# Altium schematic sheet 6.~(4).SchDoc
size 609 x 444 mm
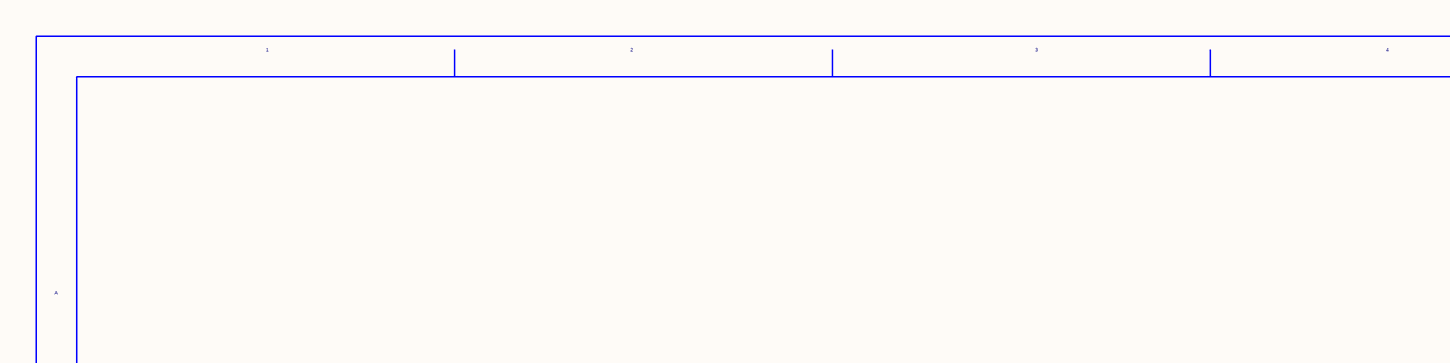
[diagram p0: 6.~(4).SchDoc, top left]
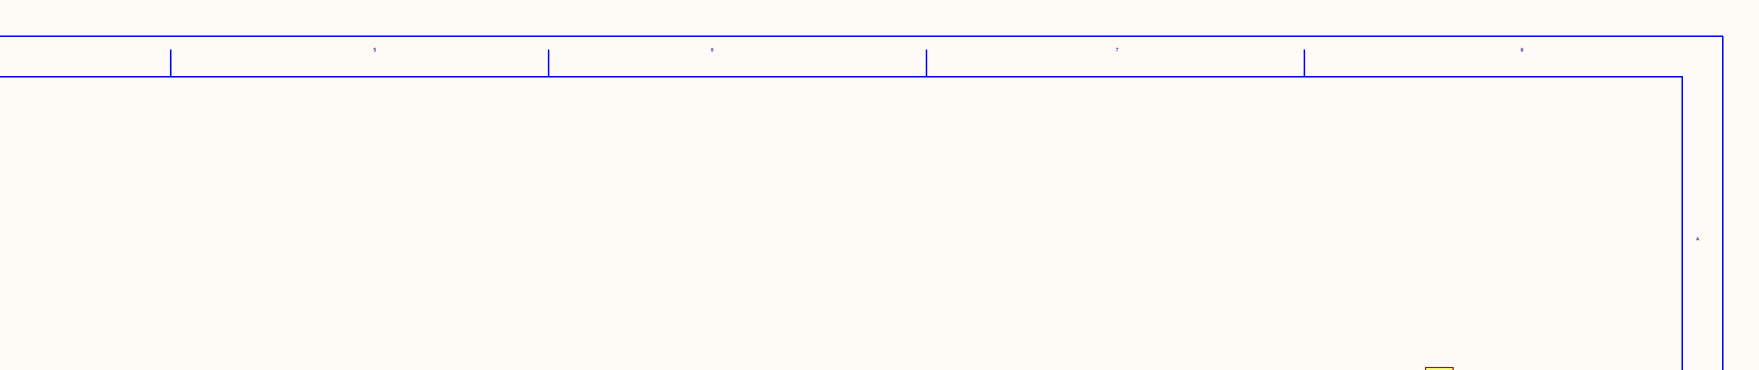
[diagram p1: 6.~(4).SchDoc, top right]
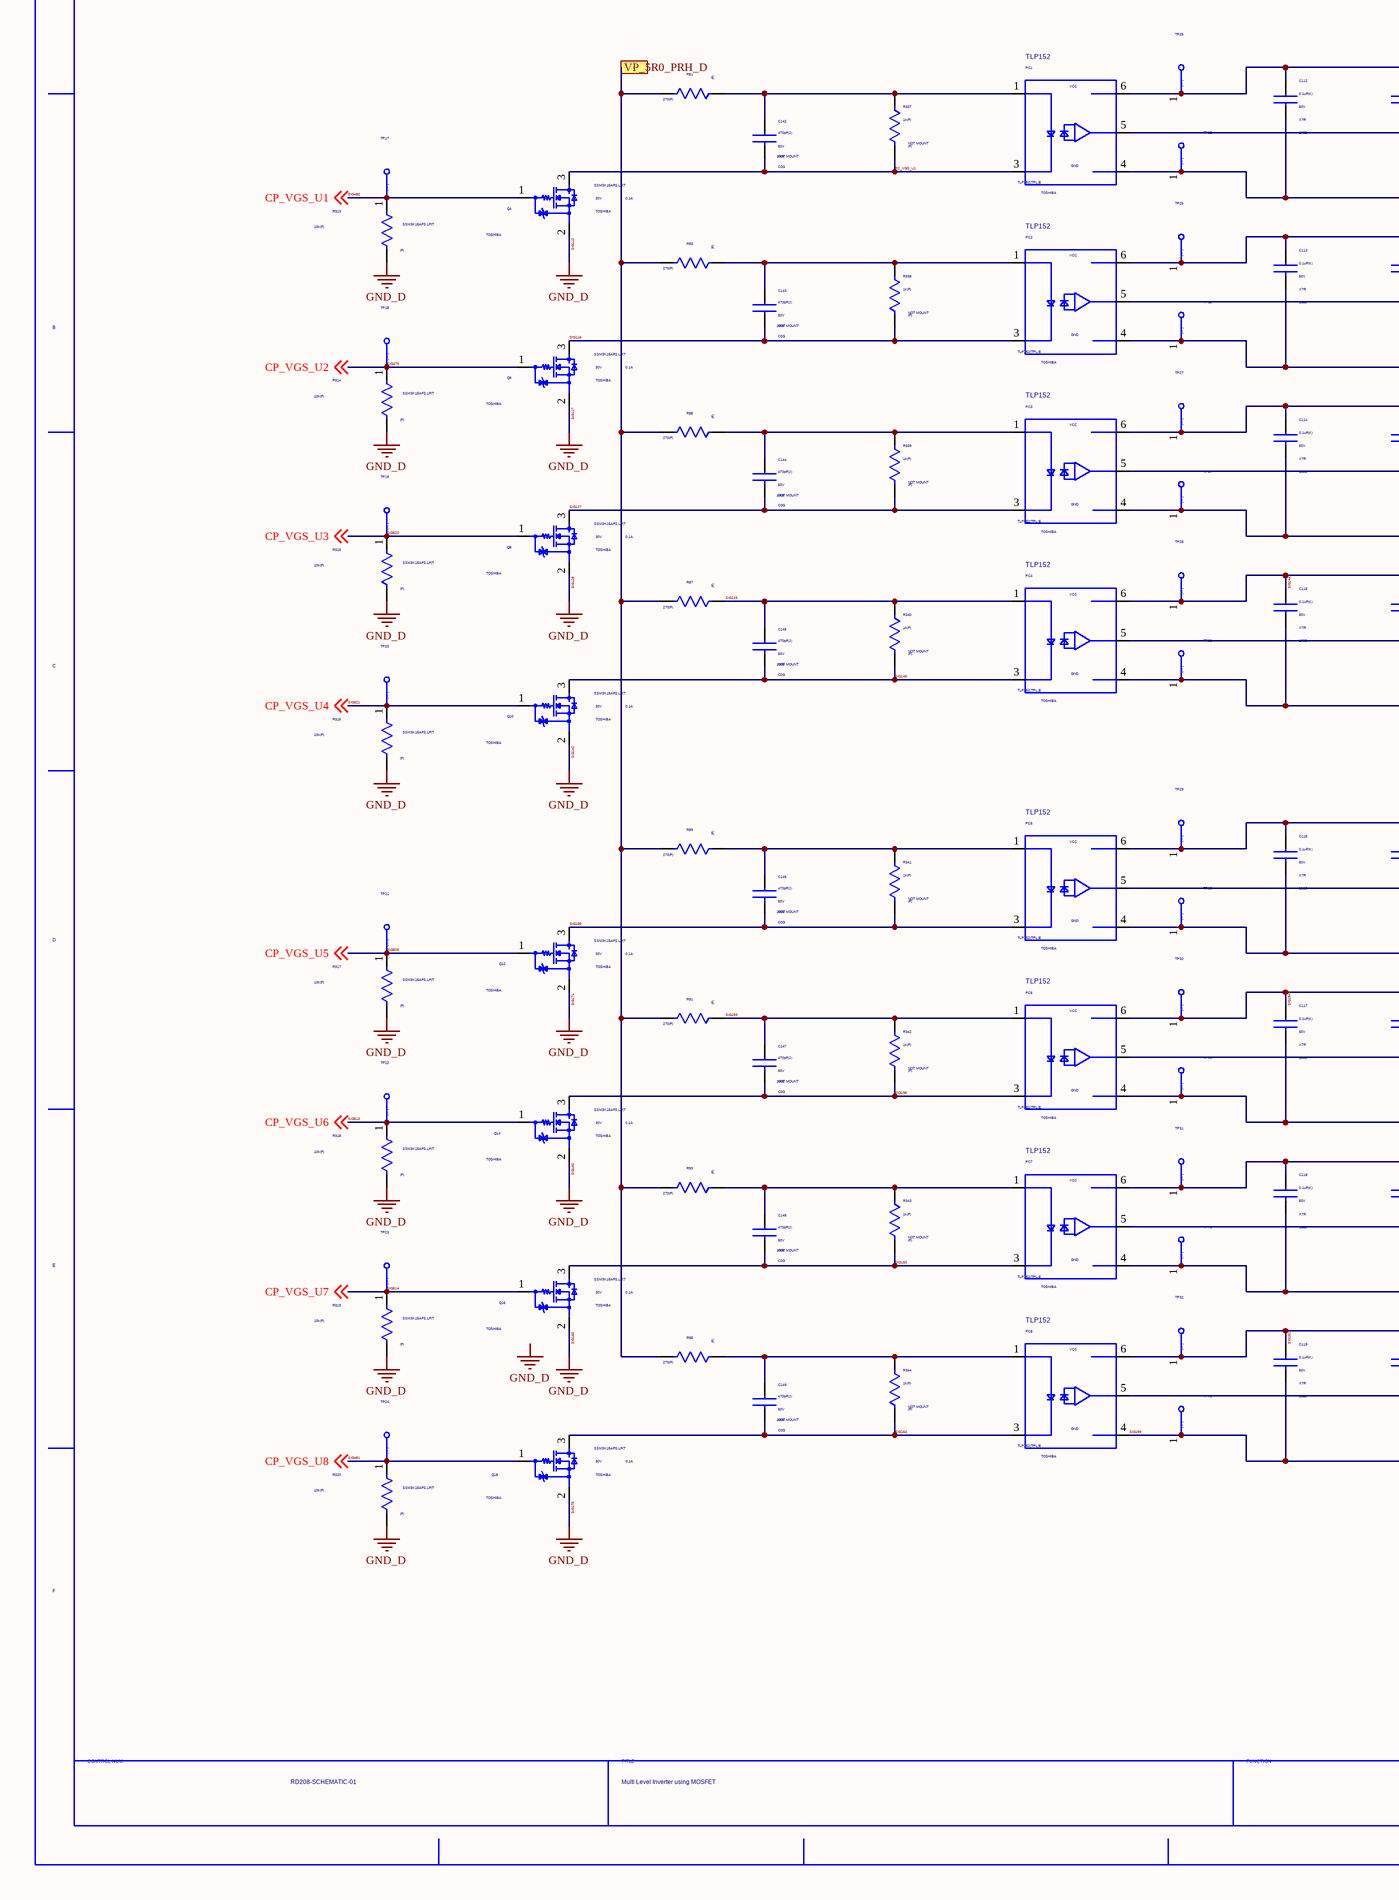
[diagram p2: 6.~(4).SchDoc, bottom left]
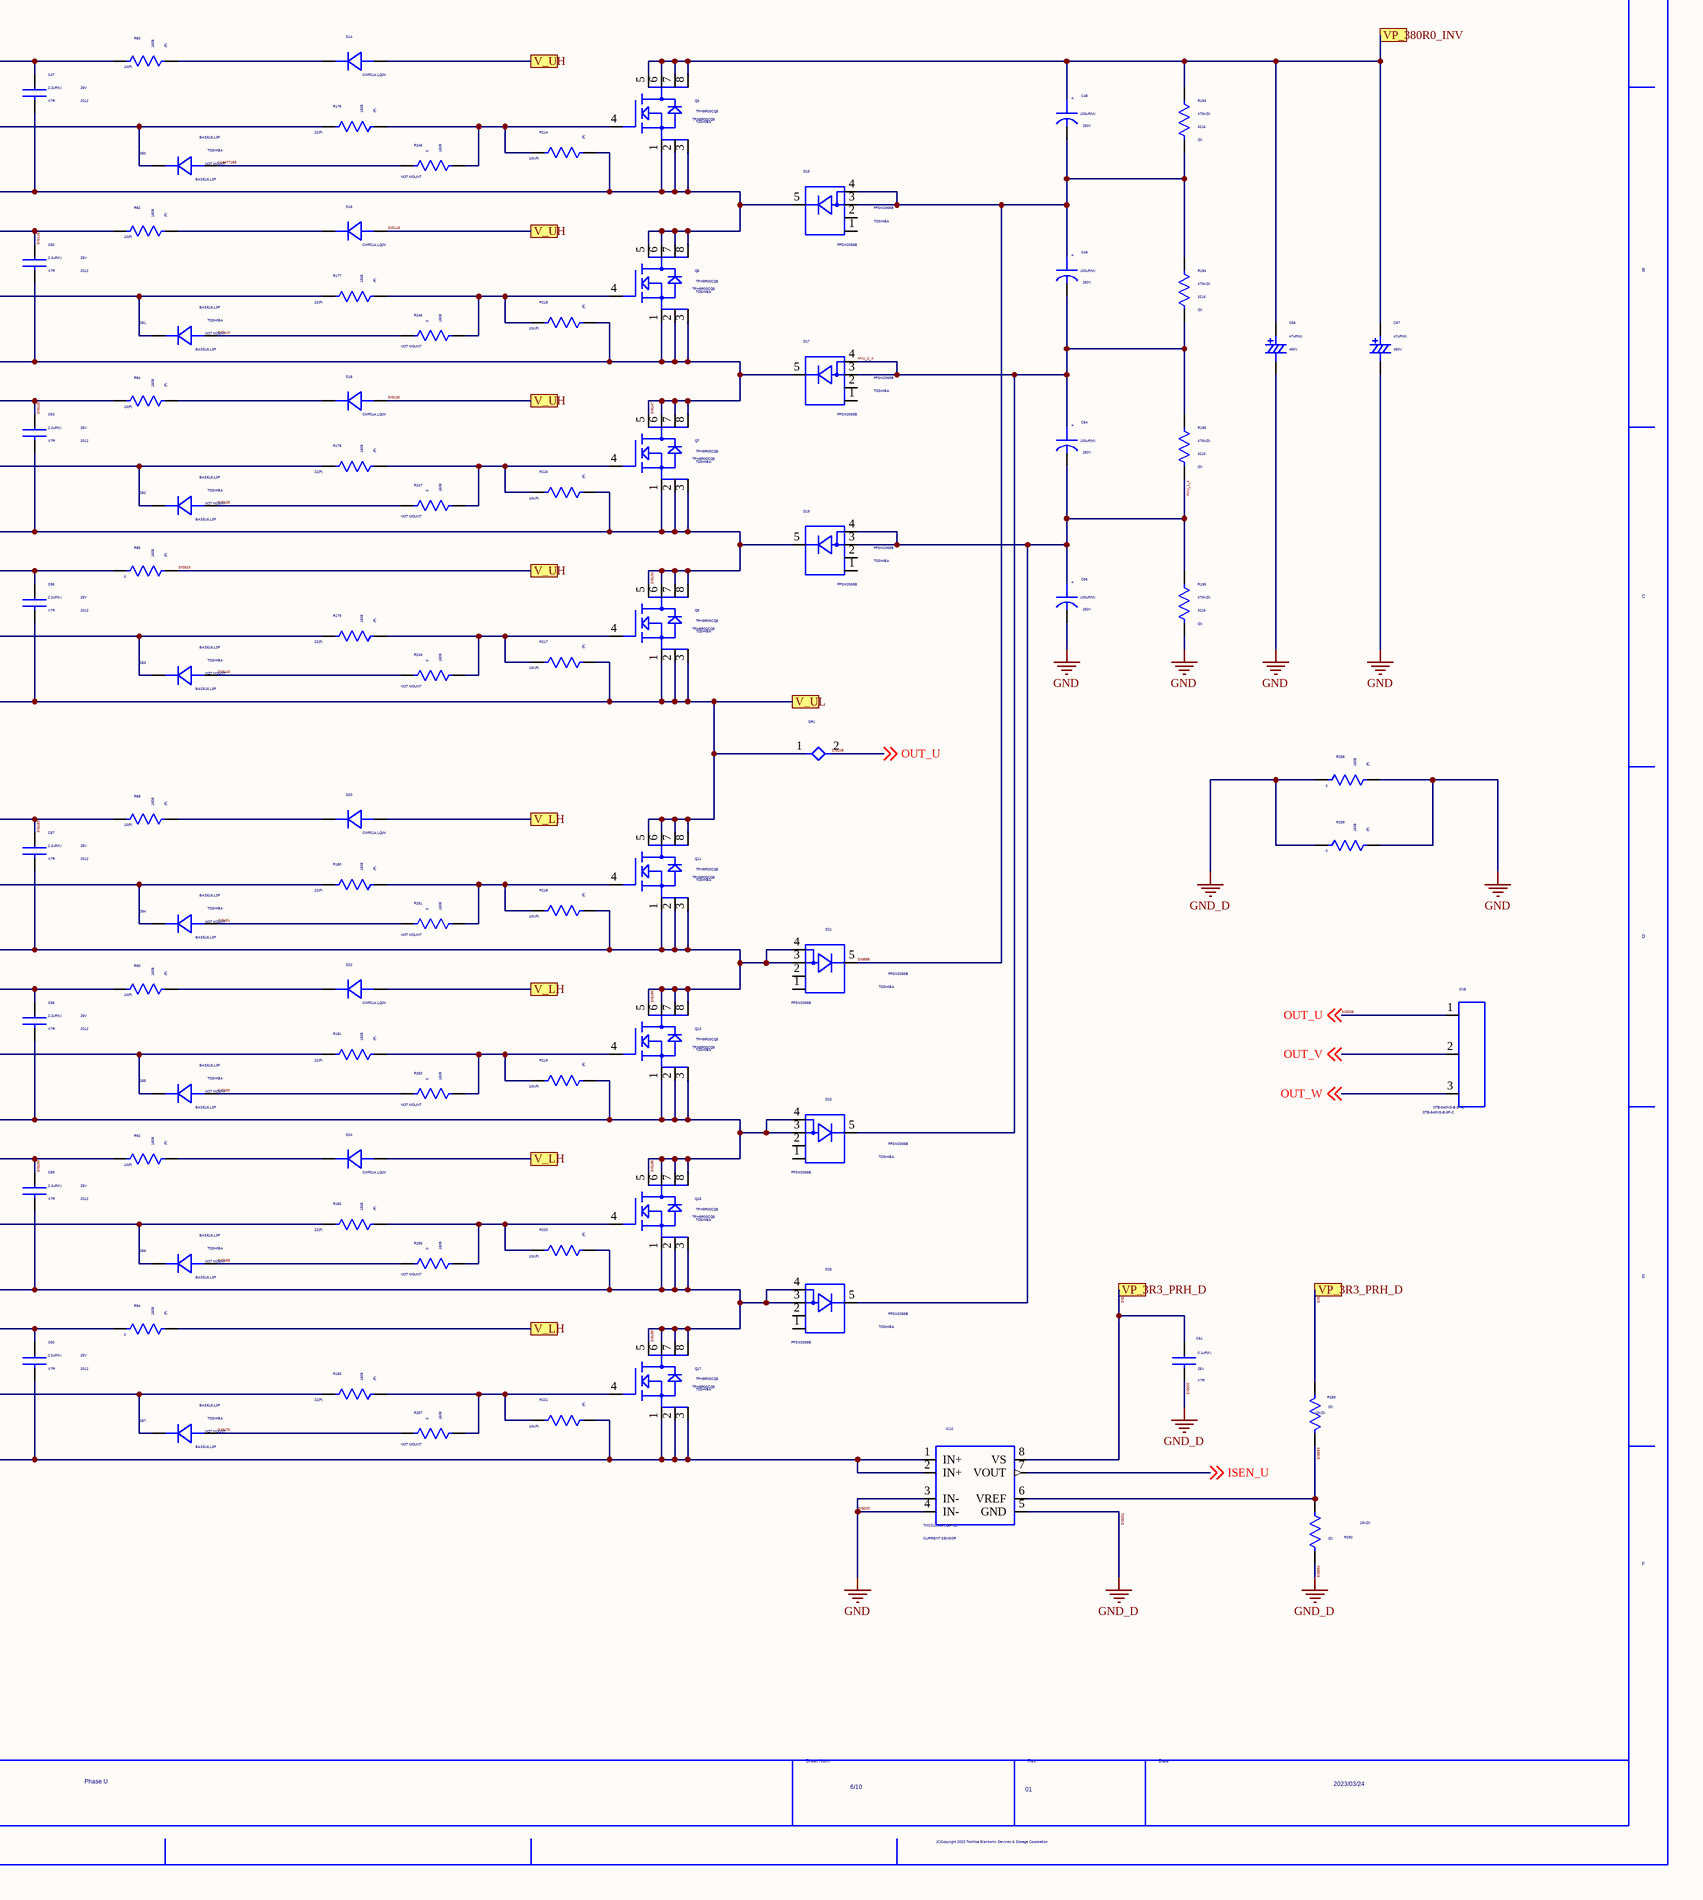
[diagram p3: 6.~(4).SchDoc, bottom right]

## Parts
C47  VAL2: 25V  SIZECODESMD: 2012  VALUE4: X7R  VAL1: 2.2uF(K)  (hidden comment: GRM21BR71E225KE11L)
C48  VAL2: 250V  VAL1: 100uF(M)  (hidden comment: EKMQ251ELL101ML25S)
C49  VAL2: 250V  VAL1: 100uF(M)  (hidden comment: EKMQ251ELL101ML25S)
C50  VAL2: 25V  SIZECODESMD: 2012  VALUE4: X7R  VAL1: 2.2uF(K)  (hidden comment: GRM21BR71E225KE11L)
C53  VAL2: 25V  SIZECODESMD: 2012  VALUE4: X7R  VAL1: 2.2uF(K)  (hidden comment: GRM21BR71E225KE11L)
C54  VAL2: 250V  VAL1: 100uF(M)  (hidden comment: EKMQ251ELL101ML25S)
C55  VAL2: 25V  SIZECODESMD: 2012  VALUE4: X7R  VAL1: 2.2uF(K)  (hidden comment: GRM21BR71E225KE11L)
C56  VAL2: 250V  VAL1: 100uF(M)  (hidden comment: EKMQ251ELL101ML25S)
C57  VAL2: 25V  SIZECODESMD: 2012  VALUE4: X7R  VAL1: 2.2uF(K)  (hidden comment: GRM21BR71E225KE11L)
C58  VAL2: 25V  SIZECODESMD: 2012  VALUE4: X7R  VAL1: 2.2uF(K)  (hidden comment: GRM21BR71E225KE11L)
C59  VAL2: 25V  SIZECODESMD: 2012  VALUE4: X7R  VAL1: 2.2uF(K)  (hidden comment: GRM21BR71E225KE11L)
C60  VAL2: 25V  SIZECODESMD: 2012  VALUE4: X7R  VAL1: 2.2uF(K)  (hidden comment: GRM21BR71E225KE11L)
C61  VAL2: 25V  VALUE4: X7R  VAL1: 0.1uF(K)  (hidden comment: GRM155R71E104KE14D)
C66  VAL2: 450V  VAL1: 47uF(M)  (hidden comment: EKXF451ELL470MM25S)
C67  VAL2: 450V  VAL1: 47uF(M)  (hidden comment: EKXF451ELL470MM25S)
C112  VAL2: 50V  SIZECODESMD: 1608  VALUE4: X7R  VAL1: 0.1uF(K)  (hidden comment: C1608X7R1H104K080AA)
C113  VAL2: 50V  SIZECODESMD: 1608  VALUE4: X7R  VAL1: 0.1uF(K)  (hidden comment: C1608X7R1H104K080AA)
C114  VAL2: 50V  SIZECODESMD: 1608  VALUE4: X7R  VAL1: 0.1uF(K)  (hidden comment: C1608X7R1H104K080AA)
C115  VAL2: 50V  SIZECODESMD: 1608  VALUE4: X7R  VAL1: 0.1uF(K)  (hidden comment: C1608X7R1H104K080AA)
C116  VAL2: 50V  SIZECODESMD: 1608  VALUE4: X7R  VAL1: 0.1uF(K)  (hidden comment: C1608X7R1H104K080AA)
C117  VAL2: 50V  SIZECODESMD: 1608  VALUE4: X7R  VAL1: 0.1uF(K)  (hidden comment: C1608X7R1H104K080AA)
C118  VAL2: 50V  SIZECODESMD: 1608  VALUE4: X7R  VAL1: 0.1uF(K)  (hidden comment: C1608X7R1H104K080AA)
C119  VAL2: 50V  SIZECODESMD: 1608  VALUE4: X7R  VAL1: 0.1uF(K)  (hidden comment: C1608X7R1H104K080AA)
C142  VAL2: 50V  SIZECODESMD: 1005  VALUE4: C0G  VAL1: 470pF(J)  NOTMOUNT: NOT MOUNT  (hidden comment: GRM1555C1H471JA01J)
C143  VAL2: 50V  SIZECODESMD: 1005  VALUE4: C0G  VAL1: 470pF(J)  NOTMOUNT: NOT MOUNT  (hidden comment: GRM1555C1H471JA01J)
C144  VAL2: 50V  SIZECODESMD: 1005  VALUE4: C0G  VAL1: 470pF(J)  NOTMOUNT: NOT MOUNT  (hidden comment: GRM1555C1H471JA01J)
C145  VAL2: 50V  SIZECODESMD: 1005  VALUE4: C0G  VAL1: 470pF(J)  NOTMOUNT: NOT MOUNT  (hidden comment: GRM1555C1H471JA01J)
C146  VAL2: 50V  SIZECODESMD: 1005  VALUE4: C0G  VAL1: 470pF(J)  NOTMOUNT: NOT MOUNT  (hidden comment: GRM1555C1H471JA01J)
C147  VAL2: 50V  SIZECODESMD: 1005  VALUE4: C0G  VAL1: 470pF(J)  NOTMOUNT: NOT MOUNT  (hidden comment: GRM1555C1H471JA01J)
C148  VAL2: 50V  SIZECODESMD: 1005  VALUE4: C0G  VAL1: 470pF(J)  NOTMOUNT: NOT MOUNT  (hidden comment: GRM1555C1H471JA01J)
C149  VAL2: 50V  SIZECODESMD: 1005  VALUE4: C0G  VAL1: 470pF(J)  NOTMOUNT: NOT MOUNT  (hidden comment: GRM1555C1H471JA01J)
CN5  VAL1: OTB-640NS-B-3P-C  (hidden comment: OTB_640NS_B_3P_C)
D14  VAL1: CMF01A,LQ(M  (hidden comment: CMF01A,LQ_M)
D15  USERCOMPTEXT3: TOSHIBA  (hidden comment: FFSM2065B)
D16  VAL1: CMF01A,LQ(M  (hidden comment: CMF01A,LQ_M)
D17  USERCOMPTEXT3: TOSHIBA  (hidden comment: FFSM2065B)
D18  VAL1: CMF01A,LQ(M  (hidden comment: CMF01A,LQ_M)
D19  USERCOMPTEXT3: TOSHIBA  (hidden comment: FFSM2065B)
D20  VAL1: CMF01A,LQ(M  (hidden comment: CMF01A,LQ_M)
D21  USERCOMPTEXT3: TOSHIBA  (hidden comment: FFSM2065B)
D22  VAL1: CMF01A,LQ(M  (hidden comment: CMF01A,LQ_M)
D23  USERCOMPTEXT3: TOSHIBA  (hidden comment: FFSM2065B)
D24  VAL1: CMF01A,LQ(M  (hidden comment: CMF01A,LQ_M)
D25  USERCOMPTEXT3: TOSHIBA  (hidden comment: FFSM2065B)
D50  USERCOMPTEXT3: TOSHIBA  NOTMOUNT: NOT MOUNT  (hidden comment: BAS516,L3F)
D51  USERCOMPTEXT3: TOSHIBA  NOTMOUNT: NOT MOUNT  (hidden comment: BAS516,L3F)
D52  USERCOMPTEXT3: TOSHIBA  NOTMOUNT: NOT MOUNT  (hidden comment: BAS516,L3F)
D53  USERCOMPTEXT3: TOSHIBA  NOTMOUNT: NOT MOUNT  (hidden comment: BAS516,L3F)
D54  USERCOMPTEXT3: TOSHIBA  NOTMOUNT: NOT MOUNT  (hidden comment: BAS516,L3F)
D55  USERCOMPTEXT3: TOSHIBA  NOTMOUNT: NOT MOUNT  (hidden comment: BAS516,L3F)
D56  USERCOMPTEXT3: TOSHIBA  NOTMOUNT: NOT MOUNT  (hidden comment: BAS516,L3F)
D57  USERCOMPTEXT3: TOSHIBA  NOTMOUNT: NOT MOUNT  (hidden comment: BAS516,L3F)
DR1  STAR2  (value not drawn)
IC10  VAL2: CURRENT SENSOR  (hidden comment: TMCS1100A1QDRQ1)
PC1  SCH_NAME: TLP152  USERCOMPTEXT3: TOSHIBA  VAL3: TLP152(TPL,E  (hidden comment: TLP152_TPL,E)
PC2  SCH_NAME: TLP152  USERCOMPTEXT3: TOSHIBA  VAL3: TLP152(TPL,E  (hidden comment: TLP152_TPL,E)
PC3  SCH_NAME: TLP152  USERCOMPTEXT3: TOSHIBA  VAL3: TLP152(TPL,E  (hidden comment: TLP152_TPL,E)
PC4  SCH_NAME: TLP152  USERCOMPTEXT3: TOSHIBA  VAL3: TLP152(TPL,E  (hidden comment: TLP152_TPL,E)
PC5  SCH_NAME: TLP152  USERCOMPTEXT3: TOSHIBA  VAL3: TLP152(TPL,E  (hidden comment: TLP152_TPL,E)
PC6  SCH_NAME: TLP152  USERCOMPTEXT3: TOSHIBA  VAL3: TLP152(TPL,E  (hidden comment: TLP152_TPL,E)
PC7  SCH_NAME: TLP152  USERCOMPTEXT3: TOSHIBA  VAL3: TLP152(TPL,E  (hidden comment: TLP152_TPL,E)
PC8  SCH_NAME: TLP152  USERCOMPTEXT3: TOSHIBA  VAL3: TLP152(TPL,E  (hidden comment: TLP152_TPL,E)
Q3  USERCOMPTEXT3: TOSHIBA  (hidden comment: TPH9R00CQ5)
Q4  VAL2: 0.1A  MANUFACTURER: TOSHIBA  SIZECODESMD: 30V  VAL1: SSM3K15AFS,LF(T  (hidden comment: SSM3K15AFS,LF_T)
Q5  USERCOMPTEXT3: TOSHIBA  (hidden comment: TPH9R00CQ5)
Q6  VAL2: 0.1A  MANUFACTURER: TOSHIBA  SIZECODESMD: 30V  VAL1: SSM3K15AFS,LF(T  (hidden comment: SSM3K15AFS,LF_T)
Q7  USERCOMPTEXT3: TOSHIBA  (hidden comment: TPH9R00CQ5)
Q8  VAL2: 0.1A  MANUFACTURER: TOSHIBA  SIZECODESMD: 30V  VAL1: SSM3K15AFS,LF(T  (hidden comment: SSM3K15AFS,LF_T)
Q9  USERCOMPTEXT3: TOSHIBA  (hidden comment: TPH9R00CQ5)
Q10  VAL2: 0.1A  MANUFACTURER: TOSHIBA  SIZECODESMD: 30V  VAL1: SSM3K15AFS,LF(T  (hidden comment: SSM3K15AFS,LF_T)
Q11  USERCOMPTEXT3: TOSHIBA  (hidden comment: TPH9R00CQ5)
Q12  VAL2: 0.1A  MANUFACTURER: TOSHIBA  SIZECODESMD: 30V  VAL1: SSM3K15AFS,LF(T  (hidden comment: SSM3K15AFS,LF_T)
Q13  USERCOMPTEXT3: TOSHIBA  (hidden comment: TPH9R00CQ5)
Q14  VAL2: 0.1A  MANUFACTURER: TOSHIBA  SIZECODESMD: 30V  VAL1: SSM3K15AFS,LF(T  (hidden comment: SSM3K15AFS,LF_T)
Q15  USERCOMPTEXT3: TOSHIBA  (hidden comment: TPH9R00CQ5)
Q16  VAL2: 0.1A  MANUFACTURER: TOSHIBA  SIZECODESMD: 30V  VAL1: SSM3K15AFS,LF(T  (hidden comment: SSM3K15AFS,LF_T)
Q17  USERCOMPTEXT3: TOSHIBA  (hidden comment: TPH9R00CQ5)
Q18  VAL2: 0.1A  MANUFACTURER: TOSHIBA  SIZECODESMD: 30V  VAL1: SSM3K15AFS,LF(T  (hidden comment: SSM3K15AFS,LF_T)
R80  SIZECODESMD: 1608  VALUE4: (F)  VAL1: 10(F)  (hidden comment: ERJ3EKF10R0V)
R81  VALUE4: (F)  VAL1: 270(F)  (hidden comment: ERJ2RKF2700X)
R82  SIZECODESMD: 1608  VALUE4: (F)  VAL1: 10(F)  (hidden comment: ERJ3EKF10R0V)
R83  VALUE4: (F)  VAL1: 270(F)  (hidden comment: ERJ2RKF2700X)
R84  SIZECODESMD: 1608  VALUE4: (F)  VAL1: 10(F)  (hidden comment: ERJ3EKF10R0V)
R85  VALUE4: (F)  VAL1: 270(F)  (hidden comment: ERJ2RKF2700X)
R86  SIZECODESMD: 1608  VALUE4: (F)  VAL1: 0  (hidden comment: ERJ3EKF10R0V)
R87  VALUE4: (F)  VAL1: 270(F)  (hidden comment: ERJ2RKF2700X)
R88  SIZECODESMD: 1608  VALUE4: (F)  VAL1: 10(F)  (hidden comment: ERJ3EKF10R0V)
R89  VALUE4: (F)  VAL1: 270(F)  (hidden comment: ERJ2RKF2700X)
R90  SIZECODESMD: 1608  VALUE4: (F)  VAL1: 10(F)  (hidden comment: ERJ3EKF10R0V)
R91  VALUE4: (F)  VAL1: 270(F)  (hidden comment: ERJ2RKF2700X)
R92  SIZECODESMD: 1608  VALUE4: (F)  VAL1: 10(F)  (hidden comment: ERJ3EKF10R0V)
R93  VALUE4: (F)  VAL1: 270(F)  (hidden comment: ERJ2RKF2700X)
R94  SIZECODESMD: 1608  VALUE4: (F)  VAL1: 0  (hidden comment: ERJ3EKF10R0V)
R95  VALUE4: (F)  VAL1: 270(F)  (hidden comment: ERJ2RKF2700X)
R176  SIZECODESMD: 1608  VALUE4: (F)  VAL1: 22(F)  (hidden comment: ERJ3EKF22R0V)
R177  SIZECODESMD: 1608  VALUE4: (F)  VAL1: 22(F)  (hidden comment: ERJ3EKF22R0V)
R178  SIZECODESMD: 1608  VALUE4: (F)  VAL1: 22(F)  (hidden comment: ERJ3EKF22R0V)
R179  SIZECODESMD: 1608  VALUE4: (F)  VAL1: 22(F)  (hidden comment: ERJ3EKF22R0V)
R180  SIZECODESMD: 1608  VALUE4: (F)  VAL1: 22(F)  (hidden comment: ERJ3EKF22R0V)
R181  SIZECODESMD: 1608  VALUE4: (F)  VAL1: 22(F)  (hidden comment: ERJ3EKF22R0V)
R182  SIZECODESMD: 1608  VALUE4: (F)  VAL1: 22(F)  (hidden comment: ERJ3EKF22R0V)
R183  SIZECODESMD: 1608  VALUE4: (F)  VAL1: 22(F)  (hidden comment: ERJ3EKF22R0V)
R193  SIZECODESMD: 3216  VALUE4: (D)  VAL1: 470k(D)  (hidden comment: HV73V2BTTD4703D)
R194  SIZECODESMD: 3216  VALUE4: (D)  VAL1: 470k(D)  (hidden comment: HV73V2BTTD4703D)
R195  SIZECODESMD: 3216  VALUE4: (D)  VAL1: 470k(D)  (hidden comment: HV73V2BTTD4703D)
R196  SIZECODESMD: 3216  VALUE4: (D)  VAL1: 470k(D)  (hidden comment: HV73V2BTTD4703D)
R214  VALUE4: (F)  VAL1: 10k(F)  (hidden comment: ERJ2RKF1002X)
R215  VALUE4: (F)  VAL1: 10k(F)  (hidden comment: ERJ2RKF1002X)
R216  VALUE4: (F)  VAL1: 10k(F)  (hidden comment: ERJ2RKF1002X)
R217  VALUE4: (F)  VAL1: 10k(F)  (hidden comment: ERJ2RKF1002X)
R218  VALUE4: (F)  VAL1: 10k(F)  (hidden comment: ERJ2RKF1002X)
R219  VALUE4: (F)  VAL1: 10k(F)  (hidden comment: ERJ2RKF1002X)
R220  VALUE4: (F)  VAL1: 10k(F)  (hidden comment: ERJ2RKF1002X)
R221  VALUE4: (F)  VAL1: 10k(F)  (hidden comment: ERJ2RKF1002X)
R245  SIZECODESMD: 1608  VAL1: 0  NOTMOUNT: NOT MOUNT  (hidden comment: ERJ3GEY0R00V)
R246  SIZECODESMD: 1608  VAL1: 0  NOTMOUNT: NOT MOUNT  (hidden comment: ERJ3GEY0R00V)
R247  SIZECODESMD: 1608  VAL1: 0  NOTMOUNT: NOT MOUNT  (hidden comment: ERJ3GEY0R00V)
R249  SIZECODESMD: 1608  VAL1: 0  NOTMOUNT: NOT MOUNT  (hidden comment: ERJ3GEY0R00V)
R251  SIZECODESMD: 1608  VAL1: 0  NOTMOUNT: NOT MOUNT  (hidden comment: ERJ3GEY0R00V)
R253  SIZECODESMD: 1608  VAL1: 0  NOTMOUNT: NOT MOUNT  (hidden comment: ERJ3GEY0R00V)
R255  SIZECODESMD: 1608  VAL1: 0  NOTMOUNT: NOT MOUNT  (hidden comment: ERJ3GEY0R00V)
R257  SIZECODESMD: 1608  VAL1: 0  NOTMOUNT: NOT MOUNT  (hidden comment: ERJ3GEY0R00V)
R289  VALUE4: (D)  VAL1: 10k(D)  (hidden comment: RK73G1ETTP1002D)
R290  VALUE4: (D)  VAL1: 10k(D)  (hidden comment: RK73G1ETTP1002D)
R298  SIZECODESMD: 1608  VALUE4: (F)  VAL1: 0  (hidden comment: ERJ3EKF10R0V)
R299  SIZECODESMD: 1608  VALUE4: (F)  VAL1: 0  (hidden comment: ERJ3EKF10R0V)
R313  VALUE4: (F)  VAL1: 10k(F)  (hidden comment: ERJ2RKF1002X)
R314  VALUE4: (F)  VAL1: 10k(F)  (hidden comment: ERJ2RKF1002X)
R315  VALUE4: (F)  VAL1: 10k(F)  (hidden comment: ERJ2RKF1002X)
R316  VALUE4: (F)  VAL1: 10k(F)  (hidden comment: ERJ2RKF1002X)
R317  VALUE4: (F)  VAL1: 10k(F)  (hidden comment: ERJ2RKF1002X)
R318  VALUE4: (F)  VAL1: 10k(F)  (hidden comment: ERJ2RKF1002X)
R319  VALUE4: (F)  VAL1: 10k(F)  (hidden comment: ERJ2RKF1002X)
R320  VALUE4: (F)  VAL1: 10k(F)  (hidden comment: ERJ2RKF1002X)
R337  VALUE4: (F)  VAL1: 1k(F)  NOTMOUNT: NOT MOUNT  (hidden comment: ERJ2RKF1001X)
R338  VALUE4: (F)  VAL1: 1k(F)  NOTMOUNT: NOT MOUNT  (hidden comment: ERJ2RKF1001X)
R339  VALUE4: (F)  VAL1: 1k(F)  NOTMOUNT: NOT MOUNT  (hidden comment: ERJ2RKF1001X)
R340  VALUE4: (F)  VAL1: 1k(F)  NOTMOUNT: NOT MOUNT  (hidden comment: ERJ2RKF1001X)
R341  VALUE4: (F)  VAL1: 1k(F)  NOTMOUNT: NOT MOUNT  (hidden comment: ERJ2RKF1001X)
R342  VALUE4: (F)  VAL1: 1k(F)  NOTMOUNT: NOT MOUNT  (hidden comment: ERJ2RKF1001X)
R343  VALUE4: (F)  VAL1: 1k(F)  NOTMOUNT: NOT MOUNT  (hidden comment: ERJ2RKF1001X)
R344  VALUE4: (F)  VAL1: 1k(F)  NOTMOUNT: NOT MOUNT  (hidden comment: ERJ2RKF1001X)
TP17  TP  (value not drawn)
TP18  TP  (value not drawn)
TP19  TP  (value not drawn)
TP20  TP  (value not drawn)
TP21  TP  (value not drawn)
TP22  TP  (value not drawn)
TP23  TP  (value not drawn)
TP24  TP  (value not drawn)
TP25  TP  (value not drawn)
TP26  TP  (value not drawn)
TP27  TP  (value not drawn)
TP28  TP  (value not drawn)
TP29  TP  (value not drawn)
TP30  TP  (value not drawn)
TP31  TP  (value not drawn)
TP32  TP  (value not drawn)
TP65  TP  (value not drawn)
TP66  TP  (value not drawn)
TP67  TP  (value not drawn)
TP68  TP  (value not drawn)
TP69  TP  (value not drawn)
TP70  TP  (value not drawn)
TP71  TP  (value not drawn)
TP72  TP  (value not drawn)
U?  DATE: 2023/03/24  TITLE: Multi Level Inverter using MOSFET  REVISION: 01  SHEETNUMBER: 6/10  DRAWINGNUMBER: RD208-SCHEMATIC-01  FUNCTION: Phase U  (hidden comment: WAKU_DEF_A3)

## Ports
V_LH, V_UH, V_UL, VP_3R3_PRH_D, VP_5R0_PRH_D, VP_380R0_INV

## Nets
SIG112: C61.2 IC10.5(GND) Q4.2(E) Q6.2(E) Q8.2(E) Q10.2(E) Q12.2(E) Q14.2(E) Q16.2(E) Q18.2(E) R290.2 R298.1 R299.1 R313.2 R314.2 R315.2 R316.2 R317.2 R318.2 R319.2 R320.2  [also labelled GND_D, SIG117, SIG128, SIG142, SIG160, SIG171, SIG175, SIG192, SIG201, SIG202, SIG554]
SIG200: C56.2 C66.2 C67.2 IC10.3(IN-) IC10.4(IN-) R196.2 R298.2 R299.2  [also labelled GND]
BS_U1: D14.K(CATHODE) R80.2
GD_U1: Q3.4(G) R176.2 R214.1 R245.2
GD_U2: Q5.4(G) R177.2 R215.1 R246.2
GD_U3: Q7.4(G) R178.2 R216.1 R247.2
GD_U5: Q11.4(G) R180.2 R218.1 R251.2
GD_U6: Q13.4(G) R181.2 R219.1 R253.2
GD_U7: Q15.4(G) R182.2 R220.1 R255.2
GD_U8: Q17.4(G) R183.2 R221.1 R257.2
HVU_1_4: C54.2 C56.1 D19.3(ANODE3) D19.4(ANODE4) D25.5(CATHODE) R195.2 R196.1
HVU_2_4: C49.2 C54.1 D17.3(ANODE3) D17.4(ANODE4) D23.5(CATHODE) R194.2 R195.1
ISEN_U: IC10.7(VOUT) ; off-sheet ISEN_U
N16677268: D50.A(ANODE) R245.1
OUT_V: CN5.2 ; off-sheet OUT_V
OUT_W: CN5.3 ; off-sheet OUT_W
PC_ANODE_U1: C142.1 PC1.1 R81.2 R337.1
PC_G_U1: C47.2 C112.2 D15.5(CATHODE) PC1.4 Q3.1(S1) Q3.2(S2) Q3.3(S3) Q5.5(D1) Q5.6(D2) Q5.7(D3) Q5.8(D4) R214.2 TP65.1
PC_GD_U1: D50.K(CATHODE) PC1.5 R176.1
PC_V_U1: C47.1 C112.1 PC1.6 R80.1 TP25.1
PC_VGS_U1: C142.2 PC1.3 Q4.3(C) R337.2
SIG113: C143.1 PC2.1 R83.2 R338.1
SIG114: D51.A(ANODE) R246.1
SIG115: C50.1 C113.1 PC2.6 R82.1 TP26.1
SIG116: C143.2 PC2.3 Q6.3(C) R338.2
SIG119: D14.A(ANODE) D16.A(ANODE) D18.A(ANODE) R86.2 ; port V_UH  [also labelled SIG130, SIG323]
SIG122: D51.K(CATHODE) PC2.5 R177.1
SIG123: D16.K(CATHODE) R82.2
SIG124: C144.1 PC3.1 R85.2 R339.1
SIG125: D52.A(ANODE) R247.1
SIG126: C53.1 C114.1 PC3.6 R84.1 TP27.1
SIG127: C144.2 PC3.3 Q8.3(C) R339.2
SIG133: C53.2 C114.2 D19.5(CATHODE) PC3.4 Q7.1(S1) Q7.2(S2) Q7.3(S3) Q9.5(D1) Q9.6(D2) Q9.7(D3) Q9.8(D4) R216.2 TP67.1
SIG134: D52.K(CATHODE) PC3.5 R178.1
SIG136: D53.K(CATHODE) PC4.5 R179.1
SIG137: D18.K(CATHODE) R84.2
SIG140: D53.A(ANODE) R249.1
SIG143: C145.1 PC4.1 R87.2 R340.1
SIG144: C55.1 C115.1 PC4.6 R86.1 TP28.1
SIG145: Q9.4(G) R179.2 R217.1 R249.2
SIG146: C145.2 PC4.3 Q10.3(C) R340.2
SIG147: C50.2 C113.2 D17.5(CATHODE) PC2.4 Q5.1(S1) Q5.2(S2) Q5.3(S3) Q7.5(D1) Q7.6(D2) Q7.7(D3) Q7.8(D4) R215.2 TP66.1
SIG149: C146.1 PC5.1 R89.2 R341.1
SIG150: C59.2 C118.2 D25.3(ANODE3) D25.4(ANODE4) PC7.4 Q15.1(S1) Q15.2(S2) Q15.3(S3) Q17.5(D1) Q17.6(D2) Q17.7(D3) Q17.8(D4) R220.2 TP71.1
SIG151: D54.A(ANODE) R251.1
SIG153: C148.2 PC7.3 Q16.3(C) R343.2
SIG154: C148.1 PC7.1 R93.2 R343.1
SIG156: C59.1 C118.1 PC7.6 R92.1 TP31.1
SIG158: D56.A(ANODE) R255.1
SIG161: C60.1 C119.1 PC8.6 R94.1 TP32.1
SIG163: C57.1 C116.1 PC5.6 R88.1 TP29.1
SIG164: C149.2 PC8.3 Q18.3(C) R344.2
SIG165: C146.2 PC5.3 Q12.3(C) R341.2
SIG166: D57.K(CATHODE) PC8.5 R183.1
SIG170: D57.A(ANODE) R257.1
SIG174: C149.1 PC8.1 R95.2 R344.1
SIG176: D24.K(CATHODE) R92.2
SIG180: C57.2 C116.2 D21.3(ANODE3) D21.4(ANODE4) PC5.4 Q11.1(S1) Q11.2(S2) Q11.3(S3) Q13.5(D1) Q13.6(D2) Q13.7(D3) Q13.8(D4) R218.2 TP69.1
SIG182: D54.K(CATHODE) PC5.5 R180.1
SIG183: D22.K(CATHODE) R90.2
SIG184: D56.K(CATHODE) PC7.5 R182.1
SIG185: C58.2 C117.2 D23.3(ANODE3) D23.4(ANODE4) PC6.4 Q13.1(S1) Q13.2(S2) Q13.3(S3) Q15.5(D1) Q15.6(D2) Q15.7(D3) Q15.8(D4) R219.2 TP70.1
SIG186: D55.K(CATHODE) PC6.5 R181.1
SIG187: D20.K(CATHODE) R88.2
SIG190: D55.A(ANODE) R253.1
SIG193: C147.1 PC6.1 R91.2 R342.1
SIG194: C58.1 C117.1 PC6.6 R90.1 TP30.1
SIG196: C147.2 PC6.3 Q14.3(C) R342.2
SIG199: C60.2 C119.2 IC10.1(IN+) IC10.2(IN+) PC8.4 Q17.1(S1) Q17.2(S2) Q17.3(S3) R221.2 TP72.1
SIG203: C61.1 IC10.8(VS) R289.2 ; port VP_3R3_PRH_D  [also labelled SIG204]
SIG208: CN5.1 DR1.2 ; off-sheet OUT_U  [also labelled OUT_U]
SIG479: Q6.1(B) R314.1 TP18.1 ; off-sheet CP_VGS_U2  [also labelled CP_VGS_U2]
SIG480: Q4.1(B) R313.1 TP17.1 ; off-sheet CP_VGS_U1  [also labelled CP_VGS_U1]
SIG481: Q18.1(B) R320.1 TP24.1 ; off-sheet CP_VGS_U8  [also labelled CP_VGS_U8]
SIG509: Q12.1(B) R317.1 TP21.1 ; off-sheet CP_VGS_U5  [also labelled CP_VGS_U5]
SIG513: Q14.1(B) R318.1 TP22.1 ; off-sheet CP_VGS_U6  [also labelled CP_VGS_U6]
SIG514: Q16.1(B) R319.1 TP23.1 ; off-sheet CP_VGS_U7  [also labelled CP_VGS_U7]
SIG521: Q10.1(B) R316.1 TP20.1 ; off-sheet CP_VGS_U4  [also labelled CP_VGS_U4]
SIG522: Q8.1(B) R315.1 TP19.1 ; off-sheet CP_VGS_U3  [also labelled CP_VGS_U3]
SIG553: IC10.6(VREF) R289.1 R290.1
SIG555: C48.2 C49.1 D15.3(ANODE3) D15.4(ANODE4) D21.5(CATHODE) R193.2 R194.1
V_LH: D20.A(ANODE) D22.A(ANODE) D24.A(ANODE) R94.2 ; port V_LH
V_UL: C55.2 C115.2 DR1.1 PC4.4 Q9.1(S1) Q9.2(S2) Q9.3(S3) Q11.5(D1) Q11.6(D2) Q11.7(D3) Q11.8(D4) R217.2 TP68.1 ; port V_UL
VP_5R0_PRH_D: R81.1 R83.1 R85.1 R87.1 R89.1 R91.1 R93.1 R95.1 ; port VP_5R0_PRH_D
VP_380R0_INV: C48.1 C66.1 C67.1 Q3.5(D1) Q3.6(D2) Q3.7(D3) Q3.8(D4) R193.1 ; port VP_380R0_INV

Not connected (* = marked no-connect by the designer): D15 1(NC1) 2(NC2); D17 1(NC1) 2(NC2); D19 1(NC1) 2(NC2); D21 1(NC1) 2(NC2); D23 1(NC1) 2(NC2); D25 1(NC1) 2(NC2)

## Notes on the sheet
- Labels drawn without touching a wire or pin: GND_D

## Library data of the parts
C47 C50 C53 C55 C57-C60 = GRM21BR71E225KE11L: MANUFACTURER: MURATA; ITEM: CAP Ceramic; TIME: 08:44:45; UPDATEUSER: t5459927; SAVECOUNT: 1; OriginalSymbolOrigin: (0,0); INSTANCENAME: INS15860000
C48 = EKMQ251ELL101ML25S: MANUFACTURER: Nippon Chemi-Con; ITEM: CAP ALUM; TIME: 08:44:45; UPDATEUSER: t5459927; SAVECOUNT: 1; OriginalSymbolOrigin: (0,2540); INSTANCENAME: INS16070082
C49 = EKMQ251ELL101ML25S: MANUFACTURER: Nippon Chemi-Con; ITEM: CAP ALUM; TIME: 08:44:45; UPDATEUSER: t5459927; SAVECOUNT: 1; OriginalSymbolOrigin: (0,2540); INSTANCENAME: INS16070102
C54 = EKMQ251ELL101ML25S: MANUFACTURER: Nippon Chemi-Con; ITEM: CAP ALUM; TIME: 08:44:45; UPDATEUSER: t5459927; SAVECOUNT: 1; OriginalSymbolOrigin: (0,2540); INSTANCENAME: INS16070122
C56 = EKMQ251ELL101ML25S: MANUFACTURER: Nippon Chemi-Con; ITEM: CAP ALUM; TIME: 08:44:45; UPDATEUSER: t5459927; SAVECOUNT: 1; OriginalSymbolOrigin: (0,2540); INSTANCENAME: INS16070142
C61 = GRM155R71E104KE14D: MANUFACTURER: MURATA; ITEM: CAP Ceramic; SIZECODESMD: 1005; TIME: 08:44:45; UPDATEUSER: t5459927; SAVECOUNT: 1; OriginalSymbolOrigin: (0,0); INSTANCENAME: INS16776295
C66 = EKXF451ELL470MM25S: MANUFACTURER: Nippon Chemi-Con; ITEM: CAP ALUM; SIZECODESMD: 18.0mm; TIME: 08:44:46; UPDATEUSER: t5459927; SAVECOUNT: 1; OriginalSymbolOrigin: (0,0); INSTANCENAME: INS16806395
C67 = EKXF451ELL470MM25S: MANUFACTURER: Nippon Chemi-Con; ITEM: CAP ALUM; SIZECODESMD: 18.0mm; TIME: 08:44:46; UPDATEUSER: t5459927; SAVECOUNT: 1; OriginalSymbolOrigin: (0,0); INSTANCENAME: INS16806405
C112-C119 = C1608X7R1H104K080AA: MANUFACTURER: TDK; ITEM: CAP Ceramic; TIME: 08:44:45; UPDATEUSER: t5459927; SAVECOUNT: 1; OriginalSymbolOrigin: (0,0); INSTANCENAME: INS16097035
C142-C149 = GRM1555C1H471JA01J: MANUFACTURER: MURATA; ITEM: CAP Ceramic; TIME: 08:44:46; UPDATEUSER: t5459927; SAVECOUNT: 1; OriginalSymbolOrigin: (0,0); INSTANCENAME: INS17224098
CN5 = OTB_640NS_B_3P_C: MANUFACTURER: OSADA; ITEM: Connector; VAL2: 11mm   x3; TIME: 08:44:46; UPDATEUSER: PS4_common_PC; UPDATETIME: 15:40:04; SAVECOUNT: 2; SAVEAREA0: -13992,-20726,15872,1136; OriginalSymbolOrigin: (0,0)
D14 D16 D18 D20 D22 D24 = CMF01A,LQ_M: MANUFACTURER: TOSHIBA; COMP: CMF01A_LQ_M; ITEM: DIODE; TIME: 08:44:46; UPDATEUSER: t5459927; SAVECOUNT: 1; OriginalSymbolOrigin: (0,0); INSTANCENAME: INS15860772
D15 D17 D19 D21 D23 D25 = FFSM2065B: MANUFACTURER: ON_SEMI; ITEM: DIODE; TIME: 08:44:45; UPDATEUSER: t5459927; SAVECOUNT: 1; SAVEAREA0: -3235,-11101,10576,-990; OriginalSymbolOrigin: (0,0); INSTANCENAME: INS16711377
D50-D57 = BAS516,L3F: COMP: BAS516_L3F; ITEM: DIODE; TIME: 08:44:45; UPDATEUSER: t5459927; SAVECOUNT: 1; OriginalSymbolOrigin: (0,0); INSTANCENAME: INS16674713
DR1 = STAR2: TIME: 12:37:47; UPDATEUSER: d5009410; UPDATETIME: 12:51:51; SAVECOUNT: 17; SAVEAREA0: -6564,-5245,9999,5672; OriginalSymbolOrigin: (-2540,2540); COMP: ONEPOINT
IC10 = TMCS1100A1QDRQ1: MANUFACTURER: TI; ITEM: IC CurrentSensor; TIME: 08:44:45; UPDATEUSER: PS4_common_PC; UPDATETIME: 16:01:14; SAVECOUNT: 3; SAVEAREA0: -10605,-15555,25377,840; OriginalSymbolOrigin: (0,0)
PC1-PC8 = TLP152_TPL,E: ITEM: Photocoupler; COMP: TLP152_TPL_E; TIME: 08:44:45; UPDATEUSER: t5459927; SAVECOUNT: 1; OriginalSymbolOrigin: (0,0); INSTANCENAME: INS15861608
Q3 Q5 Q7 Q9 Q11 Q13 Q15 Q17 = TPH9R00CQ5: ITEM: FET; ORDER: 0; TIME: 08:44:45; UPDATEUSER: t5459927; SAVECOUNT: 1; OriginalSymbolOrigin: (0,0); INSTANCENAME: INS15860992
Q4 Q6 Q8 Q10 Q12 Q14 Q16 Q18 = SSM3K15AFS,LF_T: ITEM: Digital Transistor NPN; COMP: SSM3K15AFS-123; ORDER: 0; TIME: 08:44:45; UPDATEUSER: t5459927; SAVECOUNT: 1; OriginalSymbolOrigin: (0,0); INSTANCENAME: INS15859756
R80 R82 R84 R88 R90 R92 = ERJ3EKF10R0V: MANUFACTURER: Panasonic; ITEM: Register; VAL2: 100mW; TIME: 08:44:45; UPDATEUSER: t5459927; SAVECOUNT: 1; OriginalSymbolOrigin: (0,0); INSTANCENAME: INS16646496
R81 R83 R85 R87 R89 R91 R93 R95 = ERJ2RKF2700X: MANUFACTURER: Panasonic; ITEM: Register; VAL2: 100mW; SIZECODESMD: 1005; TIME: 08:44:45; UPDATEUSER: t5459927; SAVECOUNT: 1; OriginalSymbolOrigin: (0,0); INSTANCENAME: INS16151457
R86 R94 R298 R299 = ERJ3EKF10R0V: MANUFACTURER: Panasonic; ITEM: Register; VAL2: 1/10W; COMP: ERJ3GEY0R00V; TIME: 08:44:45; UPDATEUSER: t5459927; SAVECOUNT: 1; OriginalSymbolOrigin: (0,0); INSTANCENAME: INS16646496
R176-R183 = ERJ3EKF22R0V: MANUFACTURER: Panasonic; ITEM: Register; VAL2: 100mW; TIME: 08:44:45; UPDATEUSER: t5459927; SAVECOUNT: 1; OriginalSymbolOrigin: (0,0); INSTANCENAME: INS17210794
R193 = HV73V2BTTD4703D: MANUFACTURER: KOA; ITEM: Register; VAL2: 0.33W; TIME: 08:44:45; UPDATEUSER: t5459927; SAVECOUNT: 1; OriginalSymbolOrigin: (0,0); INSTANCENAME: INS16806843
R194 = HV73V2BTTD4703D: MANUFACTURER: KOA; ITEM: Register; VAL2: 0.33W; TIME: 08:44:45; UPDATEUSER: t5459927; SAVECOUNT: 1; OriginalSymbolOrigin: (0,0); INSTANCENAME: INS16806859
R195 = HV73V2BTTD4703D: MANUFACTURER: KOA; ITEM: Register; VAL2: 0.33W; TIME: 08:44:45; UPDATEUSER: t5459927; SAVECOUNT: 1; OriginalSymbolOrigin: (0,0); INSTANCENAME: INS16806875
R196 = HV73V2BTTD4703D: MANUFACTURER: KOA; ITEM: Register; VAL2: 0.33W; TIME: 08:44:45; UPDATEUSER: t5459927; SAVECOUNT: 1; OriginalSymbolOrigin: (0,0); INSTANCENAME: INS16806891
R214-R221 = ERJ2RKF1002X: MANUFACTURER: Panasonic; ITEM: Register; VAL2: 100mW; SIZECODESMD: 1005; TIME: 08:44:45; UPDATEUSER: t5459927; SAVECOUNT: 1; OriginalSymbolOrigin: (0,0); INSTANCENAME: INS16648754
R245-R247 R249 R251 R253 R255 R257 = ERJ3GEY0R00V: MANUFACTURER: Panasonic; ITEM: Register; VAL2: 1/10W; TIME: 08:44:45; UPDATEUSER: t5459927; SAVECOUNT: 1; OriginalSymbolOrigin: (0,0); INSTANCENAME: INS16674743
R289 = RK73G1ETTP1002D: MANUFACTURER: KOA; ITEM: Register; VAL2: 100mW; SIZECODESMD: 1005; TIME: 08:44:46; UPDATEUSER: t5459927; SAVECOUNT: 1; OriginalSymbolOrigin: (0,0); INSTANCENAME: INS16808670
R290 = RK73G1ETTP1002D: MANUFACTURER: KOA; ITEM: Register; VAL2: 100mW; SIZECODESMD: 1005; TIME: 08:44:46; UPDATEUSER: t5459927; SAVECOUNT: 1; OriginalSymbolOrigin: (0,0); INSTANCENAME: INS16808683
R313-R320 = ERJ2RKF1002X: MANUFACTURER: Panasonic; ITEM: Register; VAL2: 100mW; SIZECODESMD: 1005; TIME: 08:44:45; UPDATEUSER: t5459927; SAVECOUNT: 1; OriginalSymbolOrigin: (0,0); INSTANCENAME: INS17222356
R337-R344 = ERJ2RKF1001X: MANUFACTURER: Panasonic; ITEM: Register; VAL2: 100mW; SIZECODESMD: 1005; TIME: 08:44:45; UPDATEUSER: t5459927; SAVECOUNT: 1; OriginalSymbolOrigin: (0,0); INSTANCENAME: INS17224061
TP17-TP32 TP65-TP72 = TP: TIME: 16:12:21; UPDATEUSER: fukuda-y; UPDATETIME: 16:18:11; SAVECOUNT: 2; SAVEAREA0: -242,-92,12810,7836; OriginalSymbolOrigin: (0,7620); VAL3: TH Hole dia. 1.0; COMP: TP-TH1.0-L1.6
U? = WAKU_DEF_A3: PLOTTIME: HH:MM; SAVEAREA0: -311037,-554865,914355,115662; TIME: 14:30:25; UPDATEUSER: PS4_common_PC; UPDATETIME: 08:25:02; SAVECOUNT: 18; ZONEOFFSETX: 36; ZONEOFFSETY: -24; OriginalSymbolOrigin: (12700,-12700)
